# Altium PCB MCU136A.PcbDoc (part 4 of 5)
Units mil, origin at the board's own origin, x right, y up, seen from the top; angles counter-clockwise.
Board outline 3937.01 x 4724.41 mil, 4 copper layers (Top Layer, Signal Layer 1, Signal Layer 2, Bottom Layer), stack 60 mil thick; 390 components, 224 nets, 1130 pads, 1344 vias.
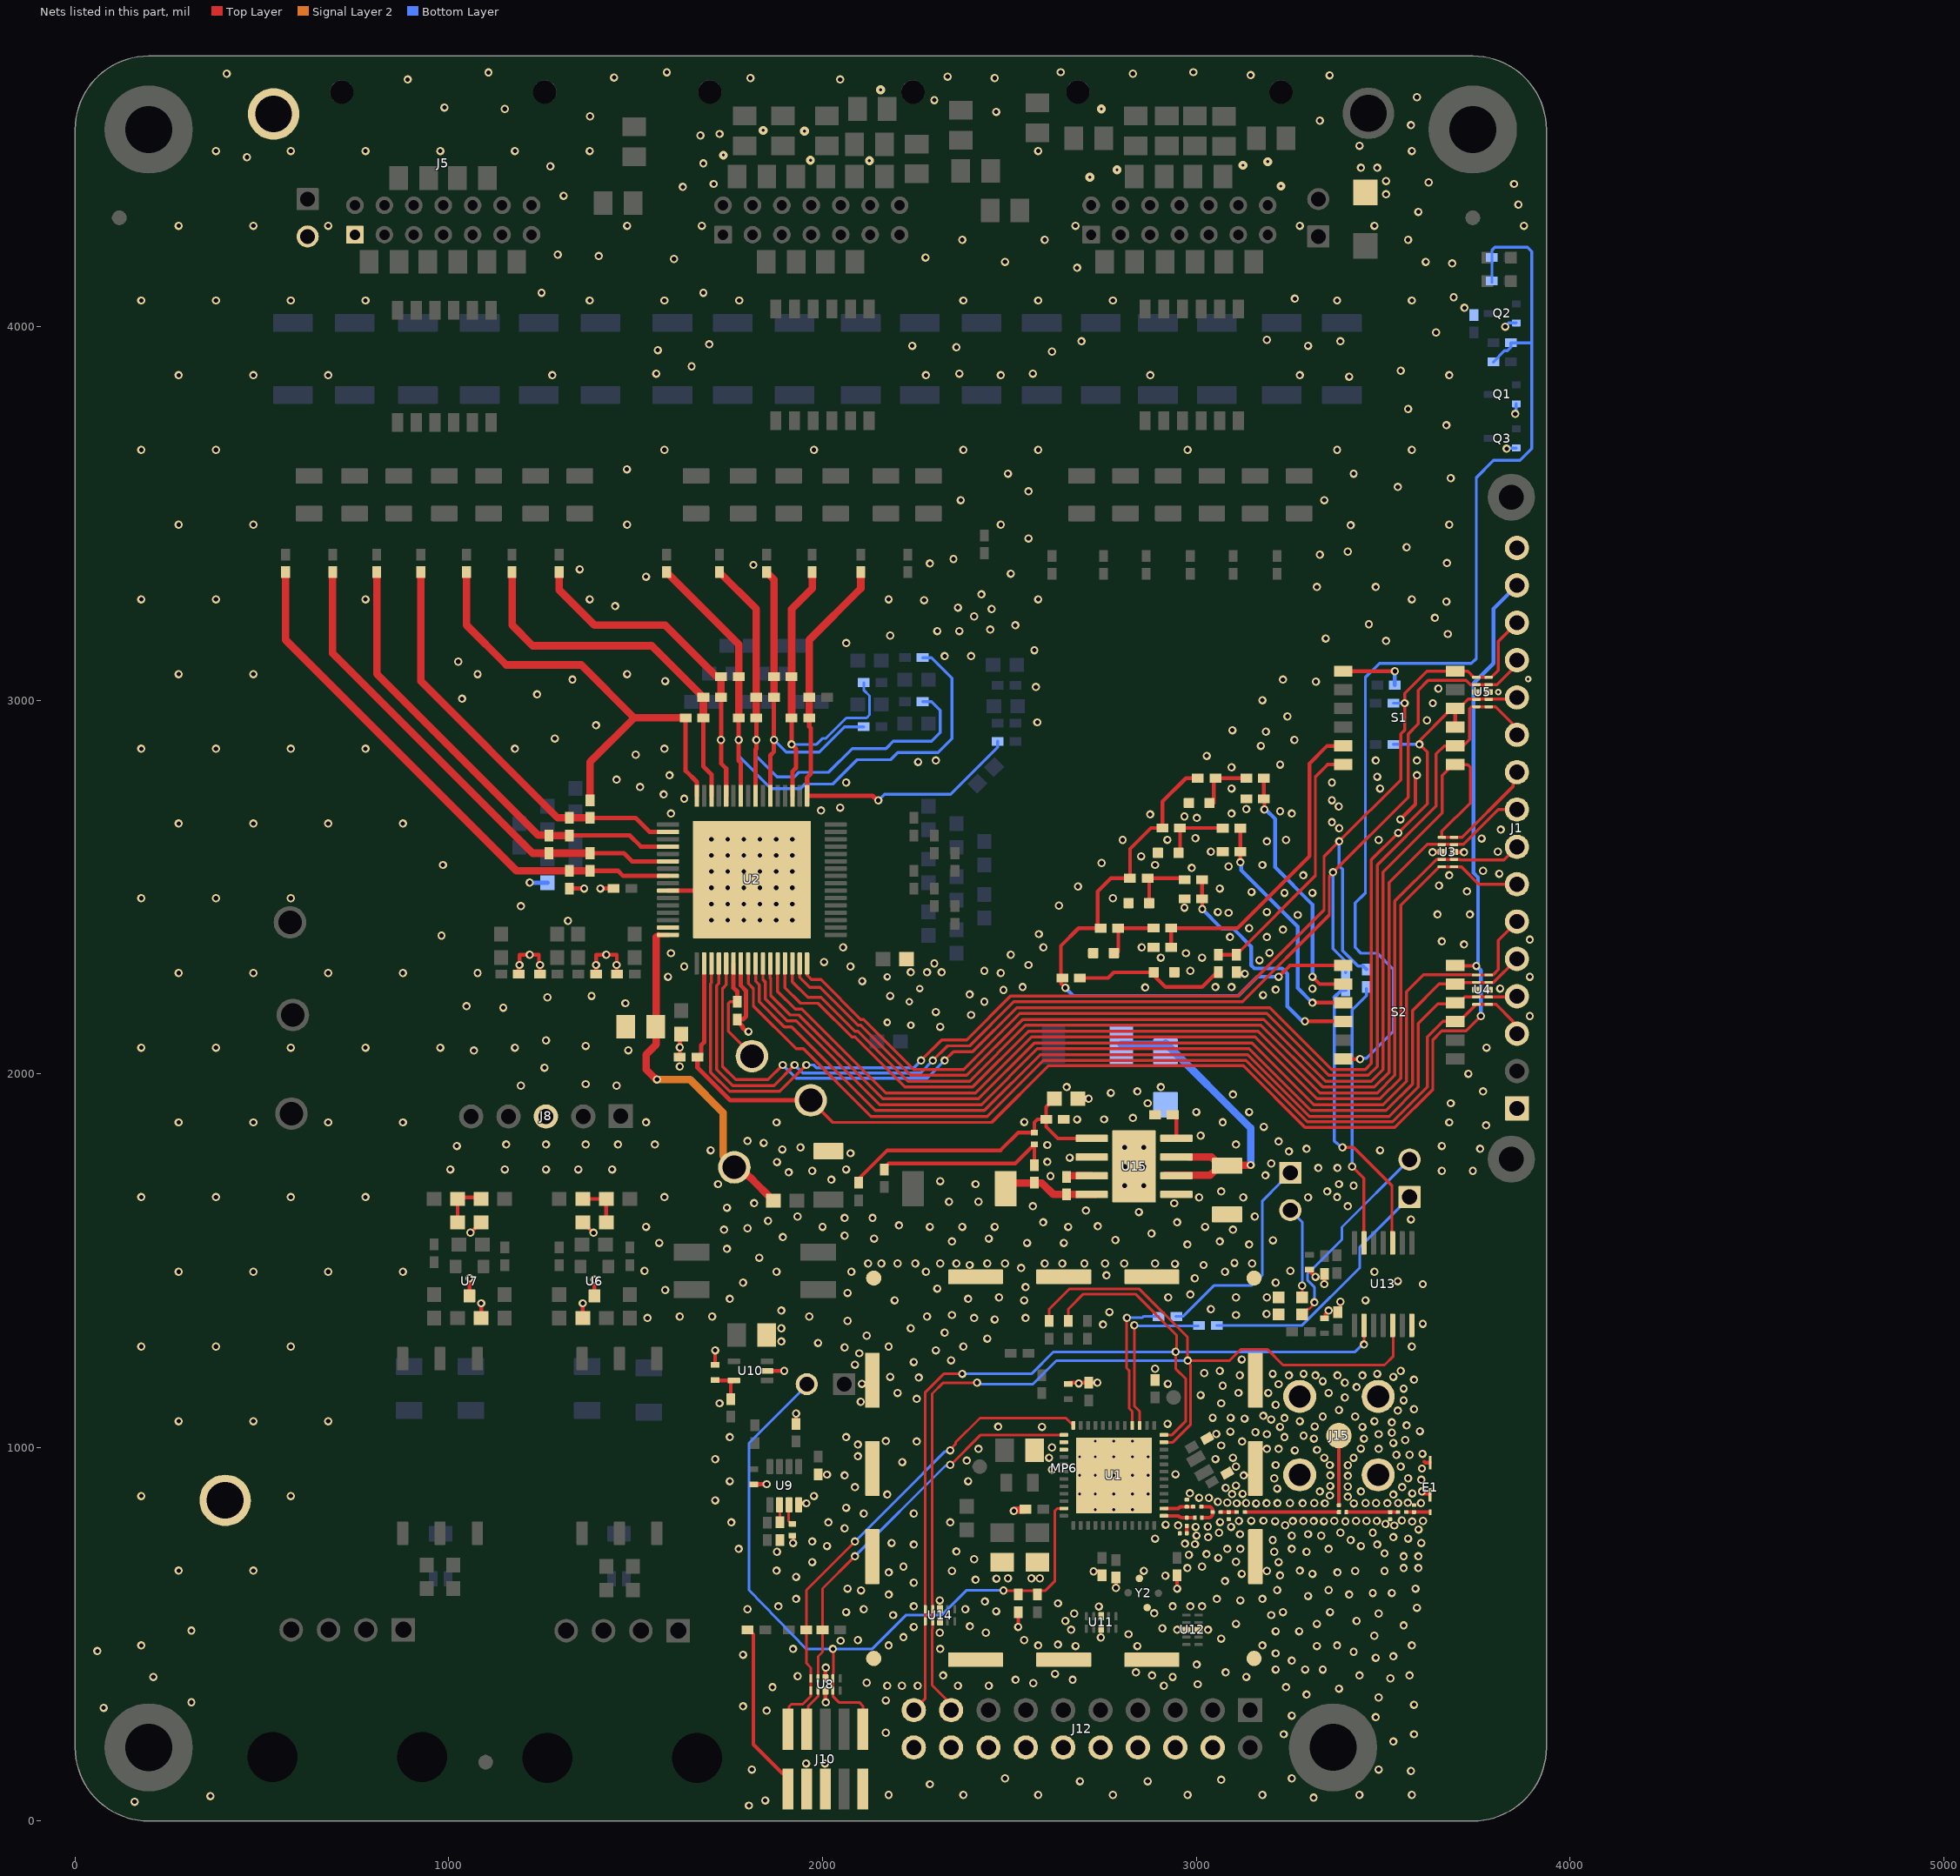
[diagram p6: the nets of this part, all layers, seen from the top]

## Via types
v1: diameter 22, hole 12, Top Layer to Bottom Layer, tented both sides, 890 vias
v2: diameter 22.01, hole 12.01, Top Layer to Bottom Layer, tented both sides, 402 vias
v3: diameter 19.68, hole 7.87, Top Layer to Bottom Layer, tented both sides, 21 vias
v4: diameter 24, hole 8, Top Layer to Bottom Layer, tented both sides, 12 vias
v5: diameter 20, hole 10, Top Layer to Bottom Layer, tented both sides, 7 vias
v6: diameter 24.8, hole 12.99, Top Layer to Bottom Layer, tented bottom, 6 vias
v7: diameter 17.46, hole 7.87, Top Layer to Bottom Layer, tented both sides, 6 vias

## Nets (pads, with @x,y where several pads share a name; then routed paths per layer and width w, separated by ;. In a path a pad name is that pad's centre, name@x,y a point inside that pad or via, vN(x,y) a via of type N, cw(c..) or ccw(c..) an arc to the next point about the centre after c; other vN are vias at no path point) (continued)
GND: C1.2 C3.1 C4.1 C7.2 C8.2 C9.2 C10.2 C11.2 C12.2 C13.2 C14.2 C15.2 C16.2 C17.2 C69.2 C70.2 C72.2 C73.1 C74.1 C75.1 C78.2 C79.1 C80.1 C81.1 C83.2 C84.2 C85.2 C86.2 C87.1 C88.2 C89.2 C90.2 C91.2 C93.1 C94.2 C95.2 C98.1 C99.1 C100.1 C101.1 C102.2 C103.2 C104.2 C105.2 C106.2 C107.2 C108.2 C109.2 C110.2 C111.2 C112.2 D1.2 D4.2 D5.1 D6.1 E1.2 E1.3 J1.1 J1.16 J5.1 J6.2 J8.3 J10.3 J10.5 J10.9 J12.4 J12.6 J12.8 J12.10 J12.12 J12.14 J12.16 J12.18 J12.20 J15.2 J15.3 J15.4 J15.5 MP6.1 MP6.2 MP6.3 MP6.4 MP6.5 MP6.6 MP6.7 MP6.8 MP6.9 MP6.10 MP6.11 MP6.12 MP6.13 MP6.14 MP6.15 MP6.16 Q1.2 Q2.2 Q3.2 R10.1 R12.1 R26.1 R147.1 R148.1 RT1.1 RT2.1 RT3.1 RT4.1 RT5.1 TP1.1 TP9.1 U1.49 U2.42 U2.55 U2.65 U3.3@3657.15,2593.74 U3.8@3690.03,2593.74 U4.3@3749.52,2225.2 U4.8@3782.39,2225.2 U5.3@3749.52,3022 U5.8@3782.39,3022 U6.3 U7.3 U8.3@2007.87,348.96 U8.8@2007.87,381.83 U9.4 U10.2 U11.3@2745.65,515.06 U11.8@2745.65,547.93 U12.3@3006.44,511.81 U12.8@2973.56,511.81 U13.7 U14.3@2314.5,534.18 U14.8@2314.5,567.06 U15.1 U15.6 U15.9 Y2.2 Y2.4 | length 1954
  Top Layer w7: v2@3062.87,1118.11 v2(3066.93,1118.11)
  Top Layer w9.45: v2(2725.23,668.29) 2740.94,668.29 2748.03,661.2 C105.2@2748.03,657.48 ; v2(2785.18,624.02) 2785.23,624.07 2785.23,650.47 C112.2@2786.68,651.92 ; v2(2948.82,622.05) C111.2@2948.82,657.48
  Top Layer w10: U7.3@1055.12,1407.48 v1(1055.12,1452.76) ; v1(1057.82,1574.8) 1058.07,1574.8 C79.1@1086.61,1603.35 ; C80.1@1086.61,1350.39 v1(1086.61,1385.83) ; C78.2@1187.31,2266.62 1187.31,2293.61 1188.98,2295.28 1188.98,2318.9 v1(1216.54,2318.9) 1240.16,2318.9 ; 1241.27,2318.9 1241.27,2290.22 1243.47,2288.02 C81.1@1243.47,2266.62 ; C73.1@1357.3,1602.36 1359.25,1602.36 1386.96,1574.65 v1(1387.16,1574.65) ; C74.1@1358.27,1346.46 v1@1358.27,1381.89 ; U6.3@1389.76,1403.54 v1(1389.76,1448.82) ; C75.1@1394.12,2266.62 1394.12,2318.9 v1(1421.26,2318.9) 1448.82,2318.9 ; 1449.24,2318.9 1449.24,2267.66 C72.2@1450.28,2266.62 ; C9.2@1618.11,2044.79 v1(1618.11,2070.87) ; C85.2@1712.6,1224.41 v1(1712.6,1259.84) ; U10.2@1854.33,1204.72 v1(1897.64,1204.72) ; v1(1921.26,744.09) 1922.17,745 v1@1922.17,754.31 ; R148.1@1929.13,1062.99 v1@1929.13,1094.49 ; U8.3@2007.87,348.96 2007.87,318.53 v1(2008.87,317.53) ; U8.8@2007.87,381.83 2007.87,409.77 v1(2008.7,410.6) ; v1(2523.62,519.68) C109.2@2523.62,559.06 ; C108.2@2661.42,1173.23 v2(2735.41,1173.23) ; C91.2@3303.15,1476.06 3303.15,1472.44 v1(3318.9,1456.69) ; v1(3342.52,1437.01) 3342.72,1437.21 3342.72,1464.37 C90.2@3342.52,1464.57 ; C88.2@3346.05,1345.45 3346.05,1357.86 v1(3354.33,1366.14) ; C89.2@3385.83,1362.2 v1(3385.83,1389.76) ; v1(3546.24,2681.1) 3586.61,2721.47 3586.61,2792.03 3590.55,2795.97 v1(3590.55,2799.21) ; v1(3603.97,881.89) 3603.97,879.65 3606.77,876.85 3620.65,876.85 E1.2@3624.54,872.96 ; 3610.27,962.02 3613.11,959.18 E1.3@3626,959.18 ; v1(3632.44,2593.17) 3632.72,2593.46 3655.76,2593.46 U3.3@3656.68,2594.38 ; U3.8@3689.76,2594.4 3690.66,2593.49 3716.55,2593.49 v1(3716.8,2593.24)
  Top Layer w11.81: C70.2@1322.83,2496.06 v2(1362.2,2496.06) ; v2(1405.51,2496.06) C14.2@1440.94,2496.06 ; U2.42@1586.61,2490.16 U2.65@1663.39,2490.16 ; v1(1618.11,2070.87) 1618.11,2102.36 C13.2@1622.05,2106.3 ; U2.55@1781.5,2295.28 1781.5,2236.22 1795.37,2222.35 1795.37,2153.64 1787.4,2145.67 C17.2@1771.65,2145.67 1771.65,2141.73 1785.91,2127.47 1785.91,2124.02 1794.87,2115.05 1800.13,2115.05 v2(1802.08,2113.1) ; C84.2@1822.83,901.57 v1(1850.39,901.57) ; U9.4@1937.01,839.26 1937.01,848.43 1938.98,850.39 v1(1956.69,850.39)
  Top Layer w19.68: v2(2511.81,829.95) 2512.44,829.95 2515.17,832.68 2541.34,832.68 C103.2@2543.31,834.65
  Bottom Layer w8: v1(3826.77,4000) 3836.61,4009.84 Q2.2@3856.3,4009.84 ; v1(3830.71,3673.23) 3832.68,3675.2 Q3.2@3856.3,3675.2 ; v1@3852.36,3765.75 3856.3,3769.69 Q1.2@3856.3,3793.31
  Bottom Layer w11.81: v2(1216.54,2511.81) C69.2@1263.78,2511.81
  other v1: 1803.15,41.34 1846.46,55.12 2287.4,98.43 2688.98,106.3 2870.08,106.3 3066.93,110.24 2488.19,114.17 3255.91,114.17 3574.8,133.86 1811.02,137.8 3488.19,137.8 1956.13,154.01 2006.31,154.01 3527.56,212.6 3234.12,232.28 3582.68,232.28 2169.29,236.22 1850.39,295.28 1787.4,307.09 3582.68,311.02 2169.29,322.83 3488.19,330.71 3295.28,338.58 3381.89,354.33 1866.14,358.27 3240.16,358.27 2173.23,362.2 2212.6,362.2 2254.78,362.19 2362.2,362.2 2444.88,362.2 2913.39,362.2 3003.94,366.14 2563.81,369.19 2118.11,370.08 2516.56,377.95 2669.29,377.95 3519.68,381.89 2937.01,385.83 3133.86,385.83 1933.37,387.67 2322.83,389.76 2881.89,389.76 3437.01,389.76 3570.87,389.76 2622.05,393.7 3212.6,405.51 3291.34,405.51 3338.58,405.51 3001.25,418.58 3255.91,429.13 3480.32,437.01 3527.56,440.94 1787.4,444.88 3212.6,448.82 3421.26,452.76 1921.26,460.63 2314.96,460.63 2677.17,468.5 2842.52,468.5 3322.83,468.5 2629.92,472.44 2048.39,482.51 2094.49,484.25 2539.37,484.25 3066.93,488.19 2744.84,491.21 2216.54,492.13 3476.38,496.06 2818.9,500 2313.68,503.94 2437.01,503.94 3212.6,507.87 3275.59,507.87 2665.35,511.81 3031.5,511.81 2909.45,515.75 2244.09,519.68 2394.42,521.03 3555.12,523.62 3106.3,527.56 3322.83,527.56 2649.61,535.43 3429.13,535.43 2188.98,551.18 3200.79,551.18 2673.23,555.12 3488.19,555.12 2062.99,559.06 3358.27,559.06 2464.71,561.33 1799.21,566.93 2110.24,566.93 2381.89,566.93 3590.55,570.87 2739.44,574.09 1881.89,574.8 2244.09,574.8 2937.01,574.8 2984.25,574.8 3015.75,574.8 2629.92,582.68 2434.59,587.35 2313.68,590.55 3118.11,590.55 1929.13,594.49 3055.12,594.49 3177.17,594.49 3299.21,602.36 2177.17,606.3 3409.45,606.3 3472.44,610.24 3523.62,610.24 2103.17,617.31 3216.54,618.11 3354.33,618.11 2066.93,622.05 3586.61,622.05 2244.09,637.8 2409.45,645.67 1929.13,653.54 2917.59,656.6 3224.41,657.48 3122.05,661.42 2177.17,665.35 3377.95,665.35 2346.46,669.29 2976.38,677.17 2216.54,681.1 3015.75,681.1 1972.44,692.91 3220.47,692.91 3106.3,693.92 2405.51,700.79 3059.06,704.72 2980.32,712.6 3027.56,714.36 3503.94,716.54 1877.95,720.47 3208.66,720.47 3295.28,720.47 1775.59,728.35 3082.95,728.35 3118.11,728.35 3255.91,728.35 3354.33,728.35 2011.81,736.22 3440.94,736.22 2244.09,740.16 3484.25,740.16 2969.69,742.22 2185.04,744.09 3602.36,744.09 1972.44,748.03 3204.72,751.97 3413.39,751.97 2889.76,755.91 3566.93,755.91 3031.76,759.7 3000.77,763.94 3255.91,763.78 3334.65,763.78 3117.32,767.72 3299.21,767.72 3060.9,771.89 3385.83,771.65 3472.44,771.65 2059.06,783.46 2998.38,787.25 3093.22,787.25 3530.03,791.04 1755.91,799.21 2015.75,799.21 2341.78,799.21 3063.81,800.23 3114.21,803.3 3258.41,802.96 3427.64,803.35 3455.67,803.2 3606.83,803.19 3147.19,803.54 2110.24,822.83 2244.09,822.83 2062.99,838.58 3108.24,850.39 3160.3,850.26 3284.86,850.65 3453.28,851.1 3540.25,850.76 3058.03,854.44 1712.6,858.27 3033.93,864.91 3405.47,868.01 3358,871.31 2173.23,874.02 3527.56,874.02 3095.97,875 3124.18,875.59 2983.04,877.32 3578.01,876.85 3330.71,881.89 3440.94,881.89 3216.54,889.76 3078.74,891.85 2086.61,893.7 3551.18,893.7 3106.3,897.68 1751.97,909.45 2389.76,909.45 3602.36,913.39 3208.66,917.32 3566.93,917.32 3405.79,923.95 2059.06,925.2 3358.64,925.06 2011.81,927.17 2614.17,940.94 3604.03,943.53 3106.3,948.82 3547.24,948.82 3405.96,952.08 3212.6,952.76 3357.5,952.73 2213.34,960.63 2385.91,964.49 1712.6,968.5 2606.3,972.44 2094.49,976.38 3535.43,980.32 3570.87,980.32 3263.78,992.13 3323.21,993.54 2417.32,996.06 3220.47,996.06 3488.19,996.06 3440.55,996.82 2614.17,1000 2094.49,1007.87 3527.56,1011.81 2251.97,1015.75 3122.56,1015.78 2169.29,1016.9 3559.06,1019.68 1751.97,1027.56 2062.99,1027.56 3287.4,1031.5 3188.98,1035.43 3488.19,1035.43 3523.62,1039.37 3158.45,1040.76 3598.43,1043.31 3224.41,1055.12 3444.65,1055.07 3317.06,1056.31 3562.99,1059.06 3523.62,1066.93 3200.79,1074.8 3129.25,1077 3091.95,1079.46 3236.22,1078.74 3179.21,1084.39 1929.13,1090.55 3539.37,1098.43 3212.6,1114.17 1724.41,1118.11 2102.36,1122.05 3555.12,1125.98 2251.97,1129.92 3397.64,1133.86 3011.73,1139.98 2200.79,1145.67 3113.06,1145.97 3354.33,1145.67 3555.12,1157.48 3429.13,1161.42 3070.87,1165.35 3220.47,1169.29 2105.24,1170.36 2685.6,1171.52 3338.58,1177.17 2181.1,1188.98 3527.56,1188.98 3116.58,1193.11 3248.03,1192.91 3318.9,1192.91 3377.95,1192.91 3444.88,1192.91 3204.72,1196.85 3287.4,1196.85 3484.25,1196.85 3021.58,1199.1 3062.99,1204.72 2889.76,1210.64 2086.61,1221.29 2244.09,1228.35 3122.05,1235.41 2098.43,1251.97 2303.15,1259.84 2059.06,1267.72 1988.19,1279.53 2440.94,1291.34 2118.11,1299.21 2326.77,1307.09 1889.76,1318.9 2236.22,1318.9 2750.52,1329.07 3606.3,1330.71 2066.93,1338.58 2460.63,1342.52 1531.5,1346.46 2405.51,1346.46 2543.31,1346.46 1618.11,1350.39 1704.72,1350.39 1964.57,1350.39 2279.53,1350.39 2346.46,1354.33 3106.3,1354.33 2767.72,1362.2 1889.76,1366.14 3039.37,1370.08 1358.27,1385.83 2192.91,1393.7 2539.37,1393.7 3452.76,1393.7 1751.97,1397.64 2389.76,1397.64 2472.44,1401.57 2925.2,1401.57 3106.3,1401.57 2984.25,1409.45 2066.93,1413.39 1578.74,1421.26 2307.09,1425.2 3606.3,1437.01 1787.4,1440.94 3212.6,1440.94 3539.37,1444.88 2996.06,1452.76 2759.84,1460.63 1523.62,1472.44 3251.97,1472.44 2531.5,1480.32 2393.7,1488.19 3019.68,1488.19 2943.09,1491.4 2122.05,1492.13 2157.48,1492.13 2200.79,1492.13 2248.03,1492.13 2314.96,1492.13 2358.27,1492.13 2440.94,1492.13 2488.19,1492.13 2594.49,1492.13 2641.73,1492.13 2700.79,1492.13 2755.91,1492.13 2807.09,1492.13 2889.76,1492.13 3149.61,1492.13 1830.71,1507.87 1744.09,1531.5 2976.38,1543.31 3141.73,1543.31 1562.99,1547.24 2547.24,1547.24 2645.67,1547.24 2346.46,1551.18 3062.99,1551.18 3205.44,1554.4 2783.46,1555.12 2137.8,1559.06 2444.88,1559.06 1893.7,1562.99 2059.06,1566.93 2880.1,1572.45 1736.22,1582.68 3098.43,1582.68 1799.21,1586.61 1527.56,1590.55 2000,1590.55 2287.4,1590.55 2374.02,1590.55 2460.63,1590.55 2657.48,1590.55 3023.62,1590.55 2736.65,1592.11 2204.72,1594.49 2590.55,1602.36 2948.82,1602.36 1854.33,1606.3 3574.8,1610.24 2059.06,1614.17 2133.86,1614.17 1933.07,1618.11 3156.67,1618.11 2846.46,1629.92 2704.72,1633.86 1744.09,1641.73 2562.99,1645.67 3405.51,1645.67 1816.91,1653.74 2940.94,1653.54 2338.58,1657.48 2417.32,1657.48 3007.87,1669.29 3125.98,1669.29 3299.21,1669.29 3066.93,1685.04 3350.39,1685.04 3421.26,1700.79 1720.47,1704.72 2409.45,1704.72 3381.89,1704.72 2314.96,1712.6 2023.62,1716.54 2610.01,1726.13 3185.04,1728.35 1909.45,1736.22 1972.44,1740.16 3657.48,1740.16 3740.16,1740.16 1003.94,1744.09 1149.61,1744.09 1259.84,1744.09 1346.46,1744.09 1437.01,1744.09 2062.99,1744.09 3326.77,1748.03 3377.95,1748.03 3200.79,1759.84 1877.95,1763.78 2601.62,1764.32 2661.42,1775.59 2074.8,1787.4 3248.03,1792.09 1700.79,1795.28 3492.13,1795.28 1892.18,1797.69 3295.28,1799.21 3759.84,1799.21 1940.94,1803.15 1021.31,1807.09 3657.48,1807.09 2601.62,1809.54 1153.54,1811.02 1259.84,1811.02 1366.14,1811.02 1452.76,1811.02 1551.18,1811.02 3106.3,1811.02 1842.52,1814.96 3220.47,1818.9 1799.21,1820.04 3011.81,1834.65 3180.88,1858.05 3775.59,1862.2 1527.56,1870.08 3070.87,1870.08 2540.03,1870.98 2681.1,1877.95 2753.41,1878.19 2830.71,1881.89 3000,1897.64 3141.73,1897.64 2870.08,1921.26 3681.1,1921.26 2712.05,1933.47 3098.43,1944.88 2771.65,1948.82 2842.52,1952.76 3767.72,1952.76 2653.16,1964.57 2905.51,1964.57 1192.91,1968.5 1448.82,1968.5 1366.14,1972.44 3728.35,2000 1255.91,2016.46 1618.11,2019.68 1066.93,2062.28 1366.14,2074.8 1259.84,2089.3 2314.96,2125.98 3892.72,2154.46 2397.64,2157.48 2303.15,2165.35 1145.67,2177.17 1047.24,2181.1 1472.44,2188.98 2433.07,2192.91 1263.78,2204.72 1381.89,2208.66 3178.84,2210.92 2393.7,2212.6 2484.25,2224.41 3212.6,2225.2 3311.02,2227.79 3813.4,2228.46 2863.49,2230.96 2535.43,2232.28 3051.18,2232.28 3094.49,2232.28 2106.3,2248.03 1586.61,2259.84 3892.72,2259.84 3129.91,2267.71 2236.22,2271.65 2279.53,2271.65 2318.9,2271.65 2433.07,2275.59 2984.25,2275.59 1629.92,2287.4 2074.8,2287.4 1188.98,2291.34 1244.09,2291.34 1393.7,2291.34 1448.82,2291.34 2551.18,2291.34 2003.94,2299.21 3169.28,2303.85 2905.51,2311.02 3015.75,2311.02 2503.94,2318.9 1594.49,2322.83 2972.44,2322.83 3196.09,2323.6 2055.12,2338.58 2591.11,2338.58 2854.33,2338.58 3716.54,2346.46 3657.48,2354.33 3892.72,2359.08 3090.55,2366.14 3188.98,2366.14 980.32,2370.08 2578.74,2374.02 3232.28,2385.83 3141.73,2389.76 1318.9,2409.45 1702.76,2411.42 1746.06,2411.42 1789.37,2411.42 1832.68,2411.42 1875.98,2411.42 1919.29,2411.42 3271.65,2425.2 3645.67,2426.51 3732.28,2426.51 3086.61,2431.1 3057.75,2433.07 3188.98,2433.07 2968.5,2444.88 1192.91,2448.82 2632.48,2450.19 1702.76,2454.72 1746.06,2454.72 1789.37,2454.72 1832.68,2454.72 1875.98,2454.72 1919.29,2454.72 3236.22,2484.25 3311.02,2484.37 3148.02,2486.6 3724.41,2488.19 3062.99,2496.06 1702.76,2498.03 1746.06,2498.03 1789.37,2498.03 1832.68,2498.03 1875.98,2498.03 1919.29,2498.03 2683.66,2501.38 3649.61,2503.94 3286.42,2531.5 3677.17,2531.5 3811.02,2535.43 1702.76,2541.34 1746.06,2541.34 1789.37,2541.34 1832.68,2541.34 1875.98,2541.34 1919.29,2541.34 3767.72,2543.31 2988.19,2551.18 3086.61,2555.12 984.25,2559.06 2889.76,2559.06 3177.17,2559.06 2746.66,2564.37 2852.55,2582.09 1702.76,2584.65 1746.06,2584.65 1789.37,2584.65 1832.68,2584.65 1875.98,2584.65 1919.29,2584.65 3039.37,2594.49 3807.09,2594.49 3188.98,2622.05 2803.15,2625.98 2922.92,2626.35 3240.16,2625.98 3488.19,2625.98 1702.76,2627.95 1746.06,2627.95 1789.37,2627.95 1832.68,2627.95 1875.98,2627.95 1919.29,2627.95 3763.78,2629.92 2997.9,2630.67 3814.96,2653.54 3382.54,2657.48 3363.1,2673.23 3001.82,2685.04 2968.5,2688.98 2876.58,2694.29 1594.49,2696.85 3094.49,2696.85 3255.91,2696.85 3224.59,2702.96 3133.86,2708.66 2047.24,2712.6 3381.45,2715.72 3363.1,2732.28 1629.92,2736.22 1574.8,2748.03 3094.49,2763.78 3492.13,2763.78 1511.81,2767.72 2062.99,2779.53 3363.1,2779.53 1448.82,2787.4 3484.25,2795.28 1590.55,2799.21 3094.49,2820.42 3224.59,2827.76 2255.91,2834.65 2303.15,2838.58 3480.32,2838.58 3590.55,2838.58 3028.04,2851.2 1500,2854.33 3173.23,2877.95 3262.77,2893.67 1283.46,2897.64 3186.41,2915.95 3096.59,2919.73 1393.7,2933.07 2574.8,2940.94 3617.5,2946 3244.09,2956.69 3177.17,3000 1035.43,3003.94 1236.22,3015.75 3648,3031.11 2570.87,3035.43 3320.27,3049.8 1578.74,3051.18 1330.71,3055.12 3232.28,3055.12 1025.25,3103.31 2326.77,3118.11 2397.64,3118.11 2566.93,3133.86 2063.59,3152.95 3507.87,3158.8 3346.46,3165.35 2181.1,3173.23 3673.23,3177.17 2307.09,3185.04 2366.14,3185.04 2448.82,3188.98 2515.75,3200.79 3462.01,3203.35 3638.61,3220.47 2405.51,3224.41 2452.76,3244.09 2362.2,3248.03 1444.88,3251.97 3669.29,3263.78 2271.65,3267.72 2425.2,3283.46 3322.83,3303.15 3480.32,3303.15 1527.56,3330.71 2503.94,3338.58 1350.39,3350.39 2287.4,3366.14 3670.98,3367.16 2350.39,3377.95 3330.71,3389.76 3405.51,3397.64 3562.99,3409.45 2551.18,3433.07 3413.39,3468.5 2370.08,3535.43 3342.52,3535.43 2551.18,3559.06 3539.37,3570.87 3681.1,3594.49 2496.06,3606.3 3421.26,3606.3 1476.38,3618.11 3669.29,3736.22 3853.61,3766.41 3566.93,3779.53 3409.45,3866.14 1555.12,3874.02 2366.14,3874.02 2562.99,3874.02 3547.24,3881.89 1649.61,3893.7 2614.17,3933.07 1559.06,3937.01 2358.27,3944.88 2240.16,3948.82 3299.21,3948.82 1696.85,3952.76 2692.91,3960.63 3385.83,3960.63 3188.98,3964.57 3641.73,3984.25 3263.78,4074.8 3688.98,4078.74 1248.03,4090.55 1681.1,4090.55 2681.1,4157.48 3685.04,4169.29 2488.19,4173.23 3614.17,4173.23 1602.36,4181.1 2275.59,4185.04 1401.12,4188.92 1291.34,4192.91 2374.02,4232.28 2594.49,4232.28 3566.93,4232.28 3594.49,4307.09 3862.2,4326.77 1307.09,4350.39 3507.87,4354.33 1625.98,4374.02 1708.66,4381.89 3850.39,4381.89 3622.05,4385.83 3507.87,4389.76 3440.94,4425.2 3484.25,4425.2 1271.65,4429.13 1681.1,4437.01 459.68,4453.51 3437.01,4484.25 1673.23,4511.81 1724.41,4515.75 3574.8,4539.37 3330.71,4551.18 1377.95,4562.99 2464.57,4574.8 1149.61,4582.68 988.19,4586.61 2299.21,4606.3 3590.55,4614.17 889.76,4661.42 2047.24,4661.42 1807.09,4665.35 2460.63,4665.35 1442.19,4666.85 2334.65,4669.29 3145.67,4673.23 3357.07,4672.84 405.51,4677.17 2830.71,4677.17 1106.02,4680.29 1583.3,4680.82 2637.18,4681.1 2992.18,4681.1
  other v2: 159.05,51.74 3314.17,62.49 362.2,66.93 2177,70.02 2377,70.02 2577,70.02 2777,70.02 2977,70.02 3177,70.02 3436.5,70.02 3577,70.02 3480.32,277.85 3255.91,282 76.3,303 311.02,317.9 209.14,385.83 2838.58,397.64 3078.74,397.64 59.31,454.72 177,470.02 2177,470.02 2577,470.02 3177,470.02 3377,470.02 3577,470.02 311.02,509.5 2948.82,511.81 2887.48,556.09 3232.28,559.06 3076.87,642.33 2465.29,648.89 2496.06,649.61 2559.06,649.61 2581.61,649.61 3311.02,661.42 3188.98,669.29 3425.2,669.29 3503.94,669.29 277,670.02 477,670.02 1877,670.02 2859.89,669.69 3277,670.02 3555.12,677.17 3594.49,677.17 3555.12,708.66 3594.49,708.66 2358.27,721.29 2996.53,740.9 3527.56,759.84 3595,780.32 3030.97,788.05 2951.54,791.16 3238.05,791.66 2918.11,793.25 3506.55,795.19 3211.25,802.31 3399.14,802.11 3577.96,801.77 3286.94,802.7 3314.27,802.71 3341.82,802.52 3369.4,803.04 3483.23,803.04 3179.95,803.79 3550.13,804.46 3188.26,850.5 3344.13,850.3 3421.73,850.13 3133.59,850.79 3217.24,850.65 3250.72,851.04 3315.81,851.07 3481.08,850.78 3511.53,850.6 3601.47,850.79 3082.95,852.02 3566.19,851.86 3007.88,865.15 177,870.02 577,870.02 1977,870.02 3405.63,895.33 3358.58,896.74 3127.13,924.96 2944.78,928.14 3051.18,969.01 3098.43,972.44 3342.52,972.44 3421.26,972.44 3605.24,982.87 3188.98,996.06 3066.93,1005.12 3314.96,1023.62 3448.82,1023.62 3236.22,1027.56 3053.64,1036.01 3091.3,1042.36 2470,1055.47 2587.43,1055.07 2923.23,1062.99 277,1070.02 477,1070.02 677,1070.02 3277,1070.02 3477,1070.02 3044.09,1079.49 3338.58,1082.68 3425.2,1082.68 3381.79,1100.08 3582.68,1102.36 3192.91,1145.67 2924.07,1170.36 3397.64,1173.23 3582.68,1181.1 2257.41,1187.1 3547.24,1204.72 2344.09,1233.1 177,1270.02 377,1270.02 577,1270.02 2177,1270.02 2377,1270.02 3577,1270.02 1889.76,1283.46 3188.26,1357.45 3188.98,1401.57 2543.31,1429.13 277,1470.02 477,1470.02 677,1470.02 877,1470.02 1877,1470.02 2077,1470.02 2277,1470.02 3077,1470.02 3477,1470.02 3102.36,1493.74 177,1670.02 377,1670.02 577,1670.02 777,1670.02 1577,1670.02 3377,1670.02 277,1870.02 477,1870.02 677,1870.02 877,1870.02 1877,1870.02 3677,1870.02 1480.32,2062.99 177,2070.02 377,2070.02 577,2070.02 777,2070.02 977,2070.02 1177,2070.02 3777,2070.02 2181.1,2208.66 277,2270.02 477,2270.02 677,2270.02 877,2270.02 1077,2270.02 2477,2270.02 2299.21,2295.28 177,2470.02 377,2470.02 577,2470.02 2777,2470.02 277,2670.02 477,2670.02 677,2670.02 877,2670.02 1996.06,2704.72 177,2870.02 377,2870.02 577,2870.02 777,2870.02 1177,2870.02 1577,2870.02 3633.11,2992.13 277,3070.02 477,3070.02 1077,3070.02 1477,3070.02 177,3270.02 377,3270.02 777,3270.02 1377,3270.02 2177,3270.02 2577,3270.02 3577,3270.02 1814.96,3362.2 277,3470.02 477,3470.02 1477,3470.02 2477,3470.02 3677,3470.02 177,3670.02 377,3670.02 1577,3670.02 1977,3670.02 2377,3670.02 2577,3670.02 2977,3670.02 3377,3670.02 3577,3670.02 277,3870.02 477,3870.02 677,3870.02 1277,3870.02 2277,3870.02 2477,3870.02 2877,3870.02 3277,3870.02 3677,3870.02 3717.75,4050.32 177,4070.02 377,4070.02 577,4070.02 777,4070.02 1377,4070.02 1577,4070.02 1777,4070.02 2377,4070.02 2577,4070.02 2777,4070.02 3377,4070.02 3577,4070.02 277,4270.02 477,4270.02 677,4270.02 1477,4270.02 1677,4270.02 2677,4270.02 3277,4270.02 3477,4270.02 3877,4270.02 377,4470.02 577,4470.02 777,4470.02 977,4470.02 1177,4470.02 1377,4470.02 2577,4470.02 3577,4470.02
  other v3: 2729.92,833.66 2779.53,833.66 2829.13,833.66 2687.99,875.59 2729.92,875.59 2779.53,875.59 2829.13,875.59 2871.06,875.59 2687.99,925.2 2729.92,925.2 2779.53,925.2 2829.13,925.2 2871.06,925.2 2687.99,974.8 2729.92,974.8 2779.53,974.8 2829.13,974.8 2871.06,974.8 2729.92,1016.73 2779.53,1016.73 2829.13,1016.73
  other v4: 3226.65,4376.02 2715.23,4400.19 2788.08,4419.89 3125.14,4431.92 3191.18,4441.46 2125.57,4444.1 1967.54,4445.58 1734.57,4458.87 1951.47,4523.49 1841.1,4525.18 2746.16,4582.43 2155.34,4633.95
  other v5: 2236.22,2129.92 2173.23,2137.8 2232.28,2192.91 2259.84,2228.35 2173.23,2259.84
  other v6: 2808.07,1700.98 2859.25,1700.98 2808.07,1752.17 2859.25,1752.17 2808.07,1803.35 2859.25,1803.35
  other v7: 3808.27,3021.84 3888.05,3056.31
GPIO0: J1.14 R5.2 R17.1 S1.12 U2.51 U5.1 U5.10 | length 3658.2
  Top Layer w8: U2.51@1702.76,2295.28 1702.76,2243.14 1700.79,2241.17 1700.79,2003.94 1751.97,1952.76 1885.83,1952.76 v2(1956.69,2023.62) ; v2(2263.78,2035.43) 2318.9,2090.55 2385.83,2090.55 2503.94,2208.66 3112.27,2208.66 3342.1,2438.5 3342.1,2581.61 v1(3382.54,2622.05) 3547.24,2786.75 3547.24,2909.56 3557.68,2920 v2(3557.68,2992.13) 3557.68,3017.94 3617.5,3077.76 S1.12@3693.31,3077.76 3726.62,3077.76 3742.4,3061.98 3742.4,3061.43 3742.46,3061.37 U5.1@3749.52,3061.37 ; U5.1@3756.64,3061.31 U5.10@3775.27,3061.31 ; U5.10@3789.51,3061.43 3808.27,3080.19 3808.27,3157.48 J1.14@3858.3,3207.48
  Bottom Layer w8: v2(1956.69,2023.62) 1976.38,2023.62 1983.81,2016.19 2244.54,2016.19 v2(2263.78,2035.43) ; v1(3382.54,2622.05) 3382.54,2556.67 3391.08,2548.13 3391.08,2330.74 3432.91,2288.91 R5.2@3446.05,2288.91 ; R17.1@3527.56,2992.13 v2(3557.68,2992.13)
  Bottom Layer w10: R5.2@3446.05,2288.91 R5.2@3455.44,2279.53
GPIO1: J1.13 R6.2 U2.52 U5.2 U5.9 | length 3446.9
  Top Layer w8: U2.52@1722.44,2295.28 1722.44,2242.13 1716.54,2236.22 1716.54,2011.81 1759.84,1968.5 1870.08,1968.5 v2(1925.2,2023.62) ; v2(2295.28,2035.43) 2334.65,2074.8 2393.7,2074.8 2511.81,2192.91 3123.84,2192.91 3356.1,2425.18 3356.1,2527.68 3366.14,2537.72 v1(3366.14,2539.37) 3566.93,2740.16 3566.93,2909.45 3594.49,2937.01 3594.49,3026.87 3620.37,3052.76 3722.45,3052.76 3733.52,3041.69 U5.2@3749.52,3041.69 U5.9@3782.39,3041.69 3805.08,3041.69 3858.27,3094.87 J1.13@3858.3,3107.48
  Bottom Layer w8: v2(1925.2,2023.62) 1946.63,2002.19 2262.03,2002.19 v2(2295.28,2035.43) ; v1(3366.14,2539.37) 3366.14,2334.57 3399.87,2300.84 R6.2@3399.87,2270.9
GPIO2: J1.12 R18.1 S1.9 S1.10 U2.53 U5.4 U5.7 | length 3578.4
  Top Layer w8: U2.53@1742.13,2295.28 1742.13,2238.19 1732.28,2228.35 1732.28,2019.68 1767.72,1984.25 1854.33,1984.25 v2(1893.7,2023.62) ; v2(2326.77,2035.43) 2350.39,2059.06 2401.57,2059.06 2519.69,2177.17 3196.85,2177.17 3362.2,2011.81 3452.76,2011.81 3468.5,2027.56 3468.5,2573.01 v1(3540.41,2644.91) 3618.11,2722.61 3618.11,2860.89 v2(3597.11,2881.89) 3599.79,2884.57 3599.79,2893.89 3672.31,2966.41 3672.31,2966.76 3683.31,2977.76 S1.10@3693.31,2977.76 3703.31,2977.76 3714.31,2988.76 3714.31,2989.1 3727.96,3002.76 3853.54,3002.76 J1.12@3858.3,3007.48
  Top Layer w10: S1.9@3693.31,2927.76 S1.10@3693.31,2977.76
  Bottom Layer w8: v2(1893.7,2023.62) 1929.13,1988.19 2279.53,1988.19 v2(2326.77,2035.43) ; R18.1@3527.56,2881.89 v2(3597.11,2881.89)
GPIO3: J1.11 S1.8 U2.64 U5.5 U5.6 | length 3080.2
  Top Layer w8: U2.64@1958.66,2295.28 1958.66,2263.78 1970.47,2251.97 1996.06,2251.97 2102.36,2145.67 2110.24,2145.67 2244.09,2011.81 2377.95,2011.81 2527.56,2161.42 3188.98,2161.42 3354.33,1996.06 3460.63,1996.06 3484.25,2019.69 3484.25,2559.06 3641.73,2716.54 3641.73,2856.01 3663.48,2877.76 S1.8@3693.31,2877.76 ; S1.8@3714.14,2877.76 3731.5,2895.11 3731.5,2977.94 3736.18,2982.63 U5.6@3782.39,2982.63 3801.12,2982.63 J1.11@3858.27,2925.48
  Top Layer w10: S1.8@3693.31,2877.76 S1.8@3714.14,2877.76 ; J1.11@3858.27,2889.76 J1.11@3858.3,2907.48 J1.11@3858.27,2925.48
GPIO4: J1.10 S1.7 U2.63 U3.1 U3.10 | length 3302.1
  Top Layer w8: U2.63@1938.98,2295.28 1938.98,2257.76 1965.71,2231.03 1993.38,2231.03 2094.49,2129.92 2102.36,2129.92 2236.22,1996.06 2385.83,1996.06 2535.43,2145.67 3181.1,2145.67 3346.46,1980.32 3468.5,1980.32 3500,2011.81 3500,2540.12 3657.67,2697.79 3657.67,2798.42 3687,2827.76 3726.18,2827.76 3733.52,2820.42 3733.52,2725.28 3657.15,2648.91 U3.1@3657.15,2633.11 U3.10@3690.03,2633.11 3711.85,2633.11 3847.37,2768.63 3847.37,2796.58 J1.10@3858.3,2807.48
GPIO5: J1.9 U2.62 U3.2 U3.9 | length 2834
  Top Layer w8: U2.62@1919.29,2295.28 1919.29,2246.06 1960.63,2204.72 1996.06,2204.72 2086.61,2114.17 2094.49,2114.17 2228.35,1980.32 2393.7,1980.32 2543.31,2129.92 3173.23,2129.92 3338.58,1964.57 3476.38,1964.57 3515.75,2003.94 3515.75,2511.81 3618.11,2614.17 3657.15,2614.17 3715.12,2614.17 3808.43,2707.48 J1.9@3858.3,2707.48
GPIO6: J1.8 U2.61 U3.4 U3.7 | length 2811.7
  Top Layer w8: U2.61@1899.61,2295.28 1899.61,2230.31 1940.94,2188.98 1988.19,2188.98 2078.74,2098.43 2086.61,2098.43 2220.47,1964.57 2401.57,1964.57 2551.18,2114.17 3165.35,2114.17 3330.71,1948.82 3484.25,1948.82 3531.5,1996.06 3531.5,2462.53 3643.02,2574.05 U3.4@3657.15,2574.05 U3.7@3690.03,2574.05 3690.09,2573.99 3706.35,2573.99 3708.1,2572.24 3823.03,2572.24 J1.8@3858.3,2607.48
GPIO7: J1.7 U2.60 U3.5 U3.6 | length 2844.3
  Top Layer w8: U2.60@1879.92,2295.28 1879.92,2220.3 1926.99,2173.23 1944.88,2173.23 2169.29,1948.82 2409.45,1948.82 2559.06,2098.43 3157.48,2098.43 3322.83,1933.07 3492.13,1933.07 3547.24,1988.19 3547.24,2451.52 U3.5@3650.03,2554.31 ; U3.5@3650.1,2554.37 U3.6@3690.03,2554.37 3709.41,2554.37 3756.3,2507.48 J1.7@3858.3,2507.48
GPIO8: J1.6 U2.59 U4.1 U4.10 | length 2718.4
  Top Layer w8: U2.59@1860.24,2295.28 1860.24,2255.91 1861.58,2254.56 1861.58,2209.28 1913.39,2157.48 1937.01,2157.48 2161.42,1933.07 2417.32,1933.07 2566.93,2082.68 3149.61,2082.68 3314.96,1917.32 3500,1917.32 3562.99,1980.31 3562.99,2161.42 3562.99,2220.06 3608.29,2265.35 3740.39,2265.35 3741.12,2264.63 U4.1@3749.52,2264.57 U4.1@3749.52,2264.57 U4.10@3782.39,2264.57 3794.14,2264.57 3808.27,2278.69 3808.27,2357.48 J1.6@3858.3,2407.48
GPIO9: J1.5 S2.11 U2.58 U4.2 U4.9 | length 2654.5
  Top Layer w8: U2.58@1840.55,2295.28 1840.55,2251.97 1846.46,2246.06 1846.46,2200.79 1905.51,2141.73 1929.13,2141.73 2153.54,1917.32 2425.2,1917.32 2574.8,2066.93 3141.73,2066.93 3307.09,1901.57 3507.87,1901.57 3578.74,1972.44 3578.74,2169.25 3649.85,2240.35 S2.11@3693.31,2240.35 ; S2.11@3697.02,2244.07 3749.52,2244.07 3782.39,2244.07 3794.86,2244.07 J1.5@3858.3,2307.48 J1.5@3847.37,2318.38
  Bottom Layer w8: J1.5@3854.33,2307.09 J1.5@3854.33,2311.42
GPIO10: J1.4 S2.10 U2.57 U4.4 U4.7 | length 2618.3
  Top Layer w8: U2.57@1820.87,2295.28 1820.87,2248.03 1830.71,2238.19 1830.71,2192.91 1897.64,2125.98 1917.32,2125.98 2141.73,1901.57 2433.07,1901.57 2582.68,2051.18 3137.68,2051.18 3302.9,1885.96 3515.89,1885.96 3594.49,1964.57 3594.49,2135.31 3646.01,2186.83 S2.10@3689.78,2186.83 ; S2.10@3693.31,2190.35 3703.31,2190.35 3718.46,2205.51 U4.4@3749.52,2205.51 U4.7@3782.39,2205.51 3856.3,2205.51 J1.4@3858.3,2207.48
  Top Layer w10: S2.10@3689.78,2186.83 S2.10@3693.31,2190.35
GPIO11: J1.3 S2.9 U2.56 U4.5 U4.6 | length 2669.6
  Top Layer w8: U2.56@1801.18,2295.28 1801.18,2242.13 1814.96,2228.35 1814.96,2181.1 1929.13,2066.93 1948.82,2066.93 2129.92,1885.83 2440.94,1885.83 2590.99,2035.87 3133.19,2035.87 3297.1,1871.96 3525.51,1871.96 3618.11,1964.57 3618.11,2098.43 3660.04,2140.35 S2.9@3693.31,2140.35 3704.05,2140.35 U4.5@3749.52,2185.83 U4.6@3782.39,2185.83 3802.36,2185.83 3847.37,2140.82 3847.37,2118.38 J1.3@3858.3,2107.48
LDO_C: C4.2 D1.1 R4.1 U15.2 U15.3 | length 848.8
  Top Layer w20: U15.2@2917.32,1728.35 3037.4,1728.35 3051.34,1742.28 3052.32,1742.28 3057.09,1747.05 3057.09,1760.83 3040.62,1777.29 U15.3@2980.15,1777.29 ; C4.2@3082.68,1753.94 3084.26,1755.52 3145.29,1755.52 v1(3145.67,1755.91)
  Bottom Layer w20: R4.1@2799.21,2078.74 D1.1@2918.07,2078.74 ; D1.1@2918.07,2082.68 3145.67,1855.08 v1(3145.67,1755.91)
LDOIN: C12.1 R3.1 TP3.1 U2.48 | length 914
  Top Layer w11.81: U2.48@1561.02,2372.05 U2.48@1586.61,2372.05
  Top Layer w15: 1555.12,2366.14 U2.48@1561.02,2372.05
  Top Layer w20: 1555.12,2366.14 1555.12,2078.74 1527.56,2051.18 1527.56,2011.81 1554.03,1985.34 1556.33,1985.34 v1@1556.33,1984.57 ; TP3.1@1797.22,1730.36 1814,1715.39 1859.95,1669.44 R3.1@1868.65,1660.74
  Signal Layer 2 w11.81: 1630.31,1984.25 1630.59,1984.54
  Signal Layer 2 w20: v1@1555.12,1984.25 1630.31,1984.25 ; 1630.59,1984.54 1645.38,1984.54 1733.74,1896.18 1733.74,1797.75 1734.21,1779.87 1740.04,1774.04 1764.62,1750.72 TP3.1@1764.81,1750.52
  other v1: 1557.26,1984.96
LED_G: D5.2 J14.2 | length 242.6
  Top Layer w7: D5.2@3283.46,1401.57 v1(3283.46,1433.07)
  Bottom Layer w7: J14.2@3251.97,1635.04 3283.46,1603.54 v1@3283.46,1437.01
LED_G_CC: R152.2 U1.16 | length 381.4
  Top Layer w7: v2(2814.54,1346.88) 2813.76,1346.1 2813.76,1212.5 2820.09,1206.17 2820.09,1105.11 2828.74,1096.46 U1.16@2828.74,1059.06
  Bottom Layer w7: v2(2814.54,1346.88) 2815.16,1347.5 2855.99,1347.5 2859.69,1351.2 2898.43,1351.2 R152.2@2899.37,1350.26
LED_G_R: J14.1 R152.1 | length 581.9
  Bottom Layer w7: R152.1@2945.44,1350.39 2964.57,1350.39 3047.24,1433.07 3147.93,1433.07 3177.17,1462.31 3177.17,1660.08 3225.94,1708.85 3225.94,1709.01 3251.81,1734.88 J14.1@3251.97,1734.88 ; R152.1@2946.49,1350.39 R152.1@2946.62,1350.26
LED_R: D6.2 J13.2 | length 549.9
  Top Layer w7: D6.2@3283.46,1358.27 3285.56,1358.27 3297.81,1370.52 3302.28,1370.52 3316.21,1384.45 v1(3316.21,1388.51)
  Bottom Layer w7: v1(3316.21,1388.51) 3316.21,1429.31 3298.4,1447.13 3298.4,1465.18 3389.76,1556.55 3389.76,1589.37 J13.2@3570.87,1770.47
LED_R_CC: R151.2 U1.15 | length 445.9
  Top Layer w7: v2(2834.26,1326.99) 2834.65,1326.61 2834.65,1110.24 2848.43,1096.46 U1.15@2848.43,1059.06
  Bottom Layer w7: v2(2834.26,1326.99) 2836.1,1325.15 2893.69,1325.15 2980.31,1325.15 R151.2@3005.55,1325.15
LED_R_R: J13.1 R151.1 | length 689.9
  Bottom Layer w7: R151.1@3055.12,1326.77 3283.46,1326.77 3437.01,1480.32 3437.01,1535.43 J13.1@3570.87,1669.29
NetC2_1: C2.1 U15.7 | length 64.6
  Top Layer w20: C2.1@2655.91,1727.17 U15.7@2720.47,1727.17
NetC2_2: C2.2 L1.2 R7.2 U15.8 | length 260.6
  Top Layer w20: L1.2@2490.16,1692.91 2504.53,1707.28 2587.43,1707.28 2617.55,1677.17 C2.2@2653.16,1677.17 U15.8@2720.47,1677.17 U15.8@2732.28,1677.17
NetC5_2: C5.2 C6.2 R7.1 | length 486.7
  Top Layer w10: C5.2@2161.42,1748.03 2165.35,1748.03 2177.17,1759.84 2515.75,1759.84 C6.2@2566.93,1811.02 R7.1@2566.93,1755.91
NetC6_1: C6.1 C7.1 R8.1 R10.2 U15.5 | length 809.9
  Top Layer w10: R8.1@2094.49,1716.54 2173.23,1795.28 2476.38,1795.28 2523.62,1842.52 C6.1@2566.93,1842.52 2566.93,1870.08 2574.8,1877.95 2598.43,1877.95 2598.43,1858.27 2629.92,1826.77 U15.5@2724.41,1826.77 ; R10.2@2598.43,1878.34 2598.43,1911.29 C7.1@2620.57,1933.43
NetC73_2: C73.2 R123.1 R125.2 | length 126
  Top Layer w10: R125.2@1358.27,1665.35 R123.1@1421.26,1665.35 C73.2@1421.26,1602.36
NetC79_2: C79.2 R134.1 R136.2 | length 126
  Top Layer w10: C79.2@1023.62,1606.3 1023.62,1669.29 R136.2@1086.61,1669.29
NetC83_1: C83.1 U9.3 | length 55
  Top Layer w7: U9.3@1909.45,847.06 1909.45,803.15 C83.1@1917.32,795.28
NetC85_1: C85.1 R146.1 U10.5 | length 90.5
  Top Layer w9.4: R146.1@1754.15,1129.6 1754.15,1170.49 U10.5@1762.8,1179.13
  Top Layer w10: C85.1@1715.59,1179.13 U10.5@1752.95,1179.13
NetC86_1: C86.1 U9.2 | length 54.1
  Top Layer w7: C86.1@1885.83,795.28 U9.2@1885.83,849.41
NetC92_1: C92.1 C97.1 L7.2 | length 252
  Top Layer w9.4: L7.2@3129.91,826.77 C92.1@3381.89,826.77
NetC92_2: C92.2 J15.1 | length 190.1
  Top Layer w9.4: C92.2@3381.89,845.35 J15.1@3381.89,1031.5 J15.1@3381.89,1035.43
NetC93_2: C93.2 L4.2 | length 21.4
  Top Layer w9.4: C93.2@2974.85,770 L4.2@2974.85,791.39
NetC96_2: C96.2 L6.1 L8.2 | length 79.5
  Top Layer w9.4: L8.2@3013.82,841.46 3033.68,841.46 cw(c3033.68,831.64) 3040.62,838.58 cw(c3032.77,830.73) 3043.87,830.73 L6.1@3043.87,826.77 3043.87,822.81 cw(c3032.77,822.81) 3040.62,814.96 cw(c3033.69,821.89) 3033.69,812.09 3030.45,812.09 C96.2@3014.84,812.09
NetC97_2: C97.2 C98.2 L5.1 | length 137.8
  Top Layer w9.4: C97.2@3401.57,826.77 C97.2@3401.65,826.77 L5.1@3539.37,826.77
NetC99_2: C99.2 L6.2 L7.1 | length 42.7
  Top Layer w9.4: L6.2@3065.53,826.77 L7.1@3108.26,826.77
NetC100_2: C100.2 E1.1 L5.2 | length 59.1
  Top Layer w9.4: L5.2@3562.99,826.77 3622.05,826.77
NetJ10_1: J10.1 R141.2 | length 481.3
  Top Layer w10: R141.2@1803.15,511.81 1814.96,500 1814.96,204.72 1892.4,127.28 1898.31,127.28 1907.87,117.72 J10.1@1907.87,77.36
NetR12_2: R12.2 U15.4 | length 74.6
  Top Layer w10: R12.2@2933.07,1893.7 2946.85,1879.92 U15.4@2946.85,1827.17 U15.4@2949.21,1827.17
NPNB: U2.47
NTC_OB1: C16.1 R27.1 S1.6 | length 699.9
  Top Layer w8: C16.1@3110.82,2322.25 3318.9,2530.34 3318.9,2795.28 3351.38,2827.76
  Top Layer w10: R27.1@3059.06,2318.9 3106.3,2318.9 C16.1@3110.24,2322.83 ; 3351.38,2827.76 S1.6@3393.31,2827.76
NTC_OB2: C15.1 R22.1 S1.5 | length 858.7
  Top Layer w10: C15.1@2933.07,2338.58 2933.07,2389.76 3110.24,2389.76 3303.15,2582.68 3303.15,2830.51 3350.39,2877.76 S1.5@3393.31,2877.76
NTC_OB3: C10.1 R15.1 S2.4 | length 661.2
  Top Layer w10: R15.1@3015.75,2519.68 C10.1@3015.75,2468.5 3016.23,2468.02 v2(3016.23,2440.78) ; v2(3290.86,2140.82) 3392.84,2140.82 S2.4@3393.31,2140.35
  Bottom Layer w10: v2(3016.23,2440.78) 3068.87,2388.14 3099.66,2388.14 3147.28,2340.52 3147.28,2290.1 3155.53,2281.85 3229.59,2281.85 3244.09,2267.34 3244.09,2180.29 3283.56,2140.82 v2(3290.86,2140.82)
NTC_OB4: C8.1 R11.1 S2.3 | length 629.3
  Top Layer w10: v2(3118.11,2566.17) R11.1@3118.11,2657.48 ; v2(3311.02,2190.35) S2.3@3393.31,2190.35
  Bottom Layer w10: v2(3118.11,2566.17) 3120.41,2563.88 3120.41,2545.33 3271.65,2394.08 3271.65,2229.72 v2(3311.02,2190.35)
NTC_OB5: C1.1 R2.1 S2.2 | length 677.6
  Top Layer w10: R2.1@3181.1,2791.34 C1.1@3181.1,2736.22 3182.48,2734.84 v2(3182.48,2707.48) ; v2(3311.02,2259.84) 3330.51,2240.35 S2.2@3393.31,2240.35
  Bottom Layer w10: v2(3182.48,2707.48) 3185.73,2707.48 3210.98,2682.23 3210.98,2553.3 3311.02,2453.25 v2(3311.02,2259.84)
NTC_T1: R25.1 R27.2 RT5.2 | length 408.9
  Top Layer w10: R25.1@2688.72,2256.31 2764.18,2256.31 2779.53,2271.65 RT5.2@2877.95,2271.65 ; RT5.2@2878.36,2271.65 2917.73,2232.28 3015.75,2232.28 R27.2@3055.12,2271.65
  Top Layer w15: R27.2@3055.12,2271.65 R27.2@3059.06,2271.65
NTC_T2: R19.1 R22.2 RT4.2 | length 163
  Top Layer w10: RT4.2@2787.4,2322.83 2791.34,2326.77 R19.1@2791.34,2389.76 R22.2@2885.83,2389.76
NTC_T3: R14.1 R15.2 RT3.2 | length 174.9
  Top Layer w10: RT3.2@2874.02,2452.76 2874.02,2519.68 R14.1@2870.08,2523.62 R15.2@2972.44,2523.62
NTC_T4: R9.1 R11.2 RT2.2 | length 178.3
  Top Layer w10: RT2.2@2956.69,2598.43 R9.1@2956.69,2658.26 3074.02,2658.26 R11.2@3074.8,2657.48
NTC_T5: R1.1 R2.2 RT1.2 | length 151.2
  Top Layer w10: RT1.2@3047.24,2724.41 3047.24,2787.4 R1.1@3051.18,2791.34 R2.2@3133.86,2791.34
PWR_LED: R20.1 R21.2 R23.2 R24.2 S2.6 | length 3032.7
  Top Layer w10: S2.6@3393.31,2040.35 3394.29,2039.37 v2(3438.33,2039.37)
  Bottom Layer w8: v2(3438.33,2039.37) 3441.01,2042.05 3455.44,2042.05 3527.56,2114.17 3527.56,2279.53 3484.25,2322.83 3440.94,2322.83 3425.2,2338.58 3425.2,2456.81 3452.76,2484.37 3452.76,3060.9 3490.62,3098.76 3736.56,3098.76 3749.52,3111.72 3749.52,3595.97 3795.28,3641.73 3866.14,3641.73 3897.64,3673.23 3897.64,3956.69 ; R20.1@3791.34,4118.11 R21.2@3791.34,4185.04 3791.34,4204.72 3799.21,4212.6 3885.83,4212.6 3897.64,4200.79 3897.64,3956.69 ; R24.2@3795.28,3905.51 3824.8,3935.04 3832.49,3935.04 3842.52,3945.07 R23.2@3842.52,3956.69 3897.64,3956.69
REF_CAP: C17.1 TP7.1 U2.54 | length 303.7
  Top Layer w8: C17.1@1771.65,2192.91 1752.72,2192.91 1748.03,2188.23 1748.03,2114.17 1803.15,2059.06 1803.15,2047.24 TP7.1@1811.02,2047.24
  Top Layer w11.81: U2.54@1761.81,2295.28 1761.81,2230.31 1771.65,2220.47 C17.1@1771.65,2192.91
RF1_N: C101.2 L8.1 U1.2 | length 80.1
  Top Layer w9.4: U1.2@2913.39,836.61 2920.5,836.61 2951.86,836.61 cw(c2963.55,824.92) 2963.55,841.46 L8.1@2992.17,841.46
RF1_P: C96.1 L4.1 U1.1 | length 83.6
  Top Layer w9.4: U1.1@2913.39,816.93 2951.94,816.93 ccw(c2963.63,828.62) 2963.63,812.09 C96.1@2995.64,812.09
RPU_10K: R16.2 S1.1 | length 175.4
  Top Layer w10: S1.1@3393.31,3077.76 v2(3531.5,3077.76)
  Bottom Layer w10: R16.2@3531.5,3040.53 v2(3531.5,3077.76)
RST_CC: C109.1 J10.10 J11.2 R158.1 U1.35 U8.4 U8.7 | length 2084.8
  Top Layer w7: J11.2@1956.69,1165.35 J11.2@1956.69,1169.29 ; v1(2027.56,460.63) 2029.2,458.99 2029.2,395.34 2027.56,393.7 2027.56,366.83 U8.4@2027.56,348.96 2027.56,333.96 2043.98,317.53 2098.43,317.53 2107.87,308.09 J10.10@2107.87,237.6 ; v2(2484.25,616.79) 2596.51,616.79 2622.05,642.33 2622.05,771.65 2622.05,830.71 2627.95,836.61 U1.35@2645.67,836.61
  Bottom Layer w7: J11.2@1957.87,1169.29 1957.87,1166.54 1803.15,1011.81 1803.15,618.11 1956.69,460.69 2027.5,460.69 v1(2027.56,460.63) 2113.95,460.69 2133.03,460.69 2223.86,551.52 2319.24,551.52 2385.83,618.11 2482.93,618.11 v2(2484.25,616.79)
TCK: J10.4 R143.1 U1.25 U8.2 U8.9 | length 1218
  Top Layer w7: J10.4@1957.87,237.6 1961.15,240.88 1961.15,306.92 1988.19,333.96 1988.19,366.83 1988.19,440.55 2000,452.36 2000,622.05 v1(2086.61,708.66) ; v1(2341.78,953.26) 2343.19,953.26 2423.39,1033.46 U1.25@2645.67,1033.46
  Bottom Layer w7: v1(2086.61,708.66) 2328.34,950.39 2338.91,950.39 v1(2341.78,953.26)
TDI: U1.27
TDO: U1.26
TMS: J10.2 R142.1 U1.24 U8.1 U8.10 | length 1345.5
  Top Layer w7: J10.2@1907.87,237.6 1910.74,240.47 1910.74,306.92 1916.15,312.33 1946.87,312.33 1968.5,333.96 ; 1968.5,334.65 1968.5,366.83 1968.5,374.02 1968.5,410.6 1956.69,422.41 1956.69,618.11 v1(2086.61,748.03) ; v1(2341.78,992.13) 2341.78,994.31 2355.89,1008.42 2355.89,1013.37 2421.26,1078.74 2651.57,1078.74 U1.24@2671.26,1059.06
  Bottom Layer w7: v1(2086.61,748.03) 2207.65,869.06 2327.84,989.26 2338.91,989.26 v1(2341.78,992.13)
TSREF: C9.1 J1.15 S2.12 TP4.1 U2.50 | length 4047.3
  Top Layer w8: TP4.1@1968.5,1929.13 2027.56,1870.08 2452.76,1870.08 2604.55,2021.87 3125.98,2021.87 3290.89,1856.96 3531.72,1856.96 3633.11,1958.35 3633.11,2090.8 3655.8,2113.48 3657.67,2115.35 3722.45,2115.35 v2(3761.56,2154.46)
  Top Layer w10: S2.12@3693.31,2290.35 3694.75,2288.91 v2(3749.46,2288.91)
  Top Layer w11.81: U2.50@1683.07,2295.28 1683.07,2084.65 1675.2,2076.77 1675.2,2050.7 1669.29,2044.79 C9.1@1665.35,2044.79 1665.35,2016.88 1752.94,1929.29 1968.35,1929.29 TP4.1@1968.5,1929.13
  Bottom Layer w10: v2(3761.56,2154.46) 3761.56,2276.81 v2(3749.46,2288.91) 3754.28,2293.74 3754.28,2525.63 3741.78,2538.13 3741.78,3045.26 3795.28,3098.75 3795.28,3244.46 J1.15@3858.3,3307.48
TSREF_J: R1.2 R9.2 R14.2 R19.2 R25.2 S2.1 | length 1601.3
  Top Layer w10: v2(2649.61,2230.31) 2637.8,2242.13 2637.8,2342.52 2685.04,2389.76 R19.2@2744.09,2389.76 ; R19.2@2736.22,2393.7 2736.22,2488.19 2771.65,2523.62 R14.2@2822.83,2523.62 2822.83,2602.36 2878.74,2658.26 R9.2@2909.45,2658.26 ; R9.2@2909.45,2661.42 2909.45,2728.35 2972.44,2791.34 R1.2@3003.94,2791.34 ; v2(3220.47,2259.84) 3250.98,2290.35 S2.1@3393.31,2290.35
  Bottom Layer w10: v2(2649.61,2230.31) 2670.96,2208.96 3073.72,2208.96 3074.02,2208.66 3112.27,2208.66 3163.45,2259.84 v2(3220.47,2259.84)
UART_RX_CC: J12.17 R153.1 U1.11 U13.5 U14.2 U14.9 | length 3072.9
  Top Layer w7: J12.17@2344.09,296.85 2344.09,312.53 2293.18,363.44 2293.18,512.43 2294.38,513.62 2294.38,531.56 2295.25,532.44 2294.81,532.87 2294.81,566.62 2295.25,567.06 2294.38,567.93 2294.38,580.87 2293.18,582.06 2293.18,1143.58 2322.02,1172.41 2412.57,1172.41 v1(2413.39,1173.23) ; R153.1@2606.3,1342.52 2606.3,1370.08 2659.86,1423.64 2848.02,1423.64 2976.38,1295.28 2976.38,1233.1 v2(2977.2,1232.28) ; U1.11@2913.39,1013.78 2937.54,1013.78 2985.33,1061.56 2985.33,1220.68 2977.2,1228.81 v2(2977.2,1232.28) ; U13.5@3527.56,1330.71 3527.56,1244.09 3503.94,1220.47 3232.28,1220.47 3190.06,1262.69 3119.53,1262.69 3089.12,1232.28 v2(2977.2,1232.28)
  Bottom Layer w7: v1(2413.39,1173.23) 2416.26,1170.36 2423.92,1170.36 2424.99,1169.29 2562.99,1169.29 2625.98,1232.28 v2(2977.2,1232.28)
UART_RX_WL: R5.1 U13.13 | length 710.4
  Top Layer w8: v2(3417.32,1751.97) 3448.82,1720.47 U13.13@3448.82,1547.24
  Bottom Layer w8: v2(3417.32,1751.97) 3417.32,2170.55 3456,2209.22 3456,2227.79 R5.1@3455.44,2228.35
UART_TX_CC: J12.19 R154.1 U1.12 U13.2 U14.1 U14.10 | length 2845.5
  Top Layer w7: J12.19@2244.09,296.85 J12.19@2245.28,298.03 ; J12.19@2248.03,295.28 2248.03,300.79 2275.28,328.04 2275.28,362.96 ; 2275.27,362.98 2275.27,1147.82 2324.3,1196.85 v1(2374.02,1196.85) ; R154.1@2657.48,1338.58 2657.48,1370.08 2698.04,1410.64 2837.39,1410.64 2947.75,1300.28 2947.75,1258.78 v2(2944.88,1255.91) 2944.88,1210.64 2972.33,1183.2 2972.33,1070.75 2935.04,1033.46 U1.12@2913.39,1033.46 ; v1(3448.82,1275.59) U13.2@3448.82,1326.77
  Bottom Layer w7: v1(2374.02,1196.85) 2559.05,1196.85 2618.11,1255.91 3425.2,1255.91 v1@3448.82,1279.53
UART_TX_WL: R6.1 U13.10 | length 773.5
  Top Layer w8: v2(3391.08,1803.15) 3421.26,1803.15 3523.62,1700.79 3523.62,1559.06 U13.10@3527.56,1555.12
  Bottom Layer w8: 3369.64,2204.72 3369.64,1819.89 3375.29,1814.24 3376.2,1814.24 3387.29,1803.15 v2(3391.08,1803.15)
  Bottom Layer w10: 3369.64,2204.72 3388.57,2223.65 R6.1@3399.87,2223.65
VC0: C68.2 C70.1 R107.2 U2.40 | length 1470.4
  Top Layer w11.81: C68.2@1377.95,2543.31 1452.76,2543.31 1466.54,2529.53 U2.40@1586.61,2529.53
  Top Layer w20: R107.2@562.99,3346.46 562.99,3161.42 582.68,3141.73 1181.1,2543.31 C70.1@1322.83,2543.31 C68.2@1377.95,2543.31
VC1: C66.2 C68.1 R103.2 U2.38 | length 1348.3
  Top Layer w11.81: C68.1@1377.95,2590.55 1468.5,2590.55 1490.16,2568.9 U2.38@1586.61,2568.9
  Top Layer w20: R103.2@688.98,3345.94 688.98,3125.98 1224.41,2590.55 C66.2@1267.72,2590.55 C68.1@1377.95,2590.55
VC2: C64.2 C66.1 R98.2 U2.36 | length 1242.8
  Top Layer w11.81: C64.2@1322.83,2637.8 1484.25,2637.8 1513.78,2608.27 U2.36@1586.61,2608.27
  Top Layer w20: R98.2@807.09,3342.52 807.09,3070.87 1238.94,2639.01 1266.5,2639.01 C66.1@1267.72,2637.8 C64.2@1322.83,2637.8
VC3: C62.2 C64.1 R95.2 U2.34 | length 1125.7
  Top Layer w11.81: C62.2@1377.95,2685.04 1500,2685.04 1537.4,2647.64 U2.34@1586.61,2647.64
  Top Layer w20: R95.2@925.2,3348.27 925.2,3051.18 1291.34,2685.04 C64.1@1322.83,2685.04 C62.2@1377.95,2685.04
VC4: C58.2 C62.1 R92.2 U2.32 | length 1333.7
  Top Layer w11.81: C58.2@1627.89,2958.66 1633.8,2952.76 C58.2@1633.86,2952.76 1633.86,2811.02 1663.39,2781.5 U2.32@1663.39,2744.09
  Top Layer w20: R92.2@1047.24,3346.46 1047.24,3200.79 1153.54,3094.49 1354.33,3094.49 1496.06,2952.76 ; C62.1@1377.95,2732.28 1377.95,2834.65 1496.06,2952.76 ; C58.2@1633.86,2952.76 1496.06,2952.76
VC5: C54.2 C58.1 R88.2 U2.30 | length 1012.4
  Top Layer w11.81: C58.1@1681.1,2952.76 1681.1,2822.83 1702.76,2801.18 U2.30@1702.76,2744.09
  Top Layer w20: R88.2@1169.29,3346.46 R88.2@1169.29,3342.52 1169.29,3200.79 1224.41,3145.67 1543.31,3145.67 1675.35,3013.62 1675.35,3009.68 1677.17,3007.87 C54.2@1681.1,3007.87 C58.1@1681.1,2952.76
VC6: C49.2 C54.1 R82.2 U2.28 | length 906.9
  Top Layer w11.81: C54.1@1728.35,3007.87 v2(1728.35,2893.7) 1728.35,2830.71 1742.13,2816.93 U2.28@1742.13,2744.09
  Top Layer w20: R82.2@1295.28,3348.27 1295.28,3295.28 1389.76,3200.79 1578.74,3200.79 1714.72,3064.8 1726.54,3064.8 C49.2@1728.35,3062.99 C54.1@1728.35,3007.87
VC7: C44.2 C49.1 C59.1 R77.2 U2.26 | length 1713.9
  Top Layer w10: C44.2@1775.59,2956.69 C44.2@1779.53,2952.76
  Top Layer w11.81: C44.2@1775.59,2956.69 v2(1775.59,2893.7) 1775.59,2838.58 1781.5,2832.68 U2.26@1781.5,2744.09
  Top Layer w20: R77.2@1582.68,3342.52 1775.59,3149.61 C49.1@1775.59,3062.99 ; C44.2@1775.59,2956.69 C49.1@1775.59,3062.99 ; 1775.59,3122.05 C49.1@1775.59,3062.99
  Bottom Layer w8: v2(1775.59,2893.7) 1775.59,2850.39 1862.2,2763.78 1940.94,2763.78 1952.76,2775.59 2007.87,2775.59 2027.56,2775.59 2092.8,2840.83 2182.47,2840.83 2201.4,2859.76 2308.58,2859.76 2346.46,2897.64 2346.46,3059.06 2291.34,3114.17 C59.1@2267.72,3114.17
VC8: C39.2 C44.1 C56.1 R70.2 U2.24 | length 1363.3
  Top Layer w11.81: U2.24@1820.87,2744.09 1820.87,2868.11 1822.83,2870.08 C44.1@1822.83,2952.76
  Top Layer w20: R70.2@1724.41,3342.52 1822.83,3244.09 C39.2@1822.83,3007.87 C44.1@1822.83,2952.76
  Bottom Layer w8: v2(1822.83,2893.7) 1822.83,2850.39 1877.95,2795.28 1925.2,2795.28 1937.01,2807.09 2007.87,2807.09 2015.75,2807.09 2079.49,2870.83 2170.04,2870.83 2188.98,2889.76 2291.34,2889.76 2314.96,2913.39 2314.96,2972.44 2291.34,2996.06 C56.1@2267.72,2996.06
VC9: C36.2 C39.1 C53.1 R67.2 U2.22 | length 892.7
  Top Layer w11.81: U2.22@1860.24,2744.09 1860.24,2852.36 1870.08,2862.2 v2(1870.08,2893.7) C39.1@1870.08,3007.87
  Top Layer w20: R67.2@1850.39,3342.52 1870.08,3322.83 C36.2@1870.08,3062.99 C39.1@1870.08,3007.87
  Bottom Layer w8: v2(1870.08,2893.7) 1902.89,2860.89 1990.81,2860.89 2059.06,2929.13 C53.1@2110.24,2929.13
VC10: C34.2 C36.1 C50.1 R63.2 U2.19 | length 968.6
  Top Layer w11.81: C34.2@1917.32,2952.76 v2(1917.32,2881.89) 1917.32,2881.68 1929.13,2869.87 1929.13,2818.9 1919.29,2809.05 U2.19@1919.29,2744.09
  Top Layer w20: C34.2@1917.32,2952.76 C36.1@1917.32,3062.99 1917.32,3244.09 1972.44,3299.21 R63.2@1972.44,3342.52 R63.2@1972.44,3346.46
  Bottom Layer w7: v2(1917.32,2881.89) 1984.25,2881.89 2000.75,2898.39 2009.22,2898.39 2063.59,2952.76 2118.11,2952.76 2125.98,2960.63 2125.98,3011.81 2110.24,3027.56 C50.1@2110.24,3047.24
VC11: C32.2 C34.1 C46.1 R58.2 U2.17 | length 1250.8
  Top Layer w11.81: C34.1@1964.57,2952.76 1964.57,2929.13 1968.5,2925.2 1968.5,2803.15 1958.66,2793.31 U2.17@1958.66,2744.09 2134.13,2744.09 2146.4,2731.83 v2(2149.15,2731.83)
  Top Layer w20: C34.1@1964.57,2952.76 C32.2@1964.57,3007.87 1964.57,3161.42 2102.36,3299.21 R58.2@2102.36,3342.52
  Bottom Layer w8: v2(2149.15,2731.83) 2149.29,2731.83 2165.49,2748.03 2342.52,2748.03 2456.69,2862.2 2468.5,2874.02 C46.1@2468.5,2889.76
